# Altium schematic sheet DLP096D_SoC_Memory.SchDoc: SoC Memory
size 431 x 279 mm; Date: Not shown in title block; ApprovedBy: Not shown in title block; CheckedBy: Not shown in title block; Author: Not shown in title block; CompanyName: Not shown in title block; Engineer: Not shown in title block; Organization: Not shown in title block; Address1: Not shown in title block; Address2: Not shown in title block; Address3: Not shown in title block; Address4: Not shown in title block; DocumentNumber: 7; Revision: Use project parameter SCH_Rev; SheetNumber: 7; SheetTotal: 10; PageSetup: Record=PageOptions¦CenterHorizontal=True¦CenterVertical=True¦PrintScale=1.00¦XCorrection=1.00¦YCorrection=1.00¦PrintKind=0¦BorderSize=5000000¦LeftOffset=0¦BottomOffset=0¦Orientation=2¦PaperLength=1000¦PaperWidth=1000¦Scale=100¦PaperSource=15¦PrintQuality=600¦MediaType=1¦DitherType=10¦PaperKind=Letter¦PrintScaleMode=1
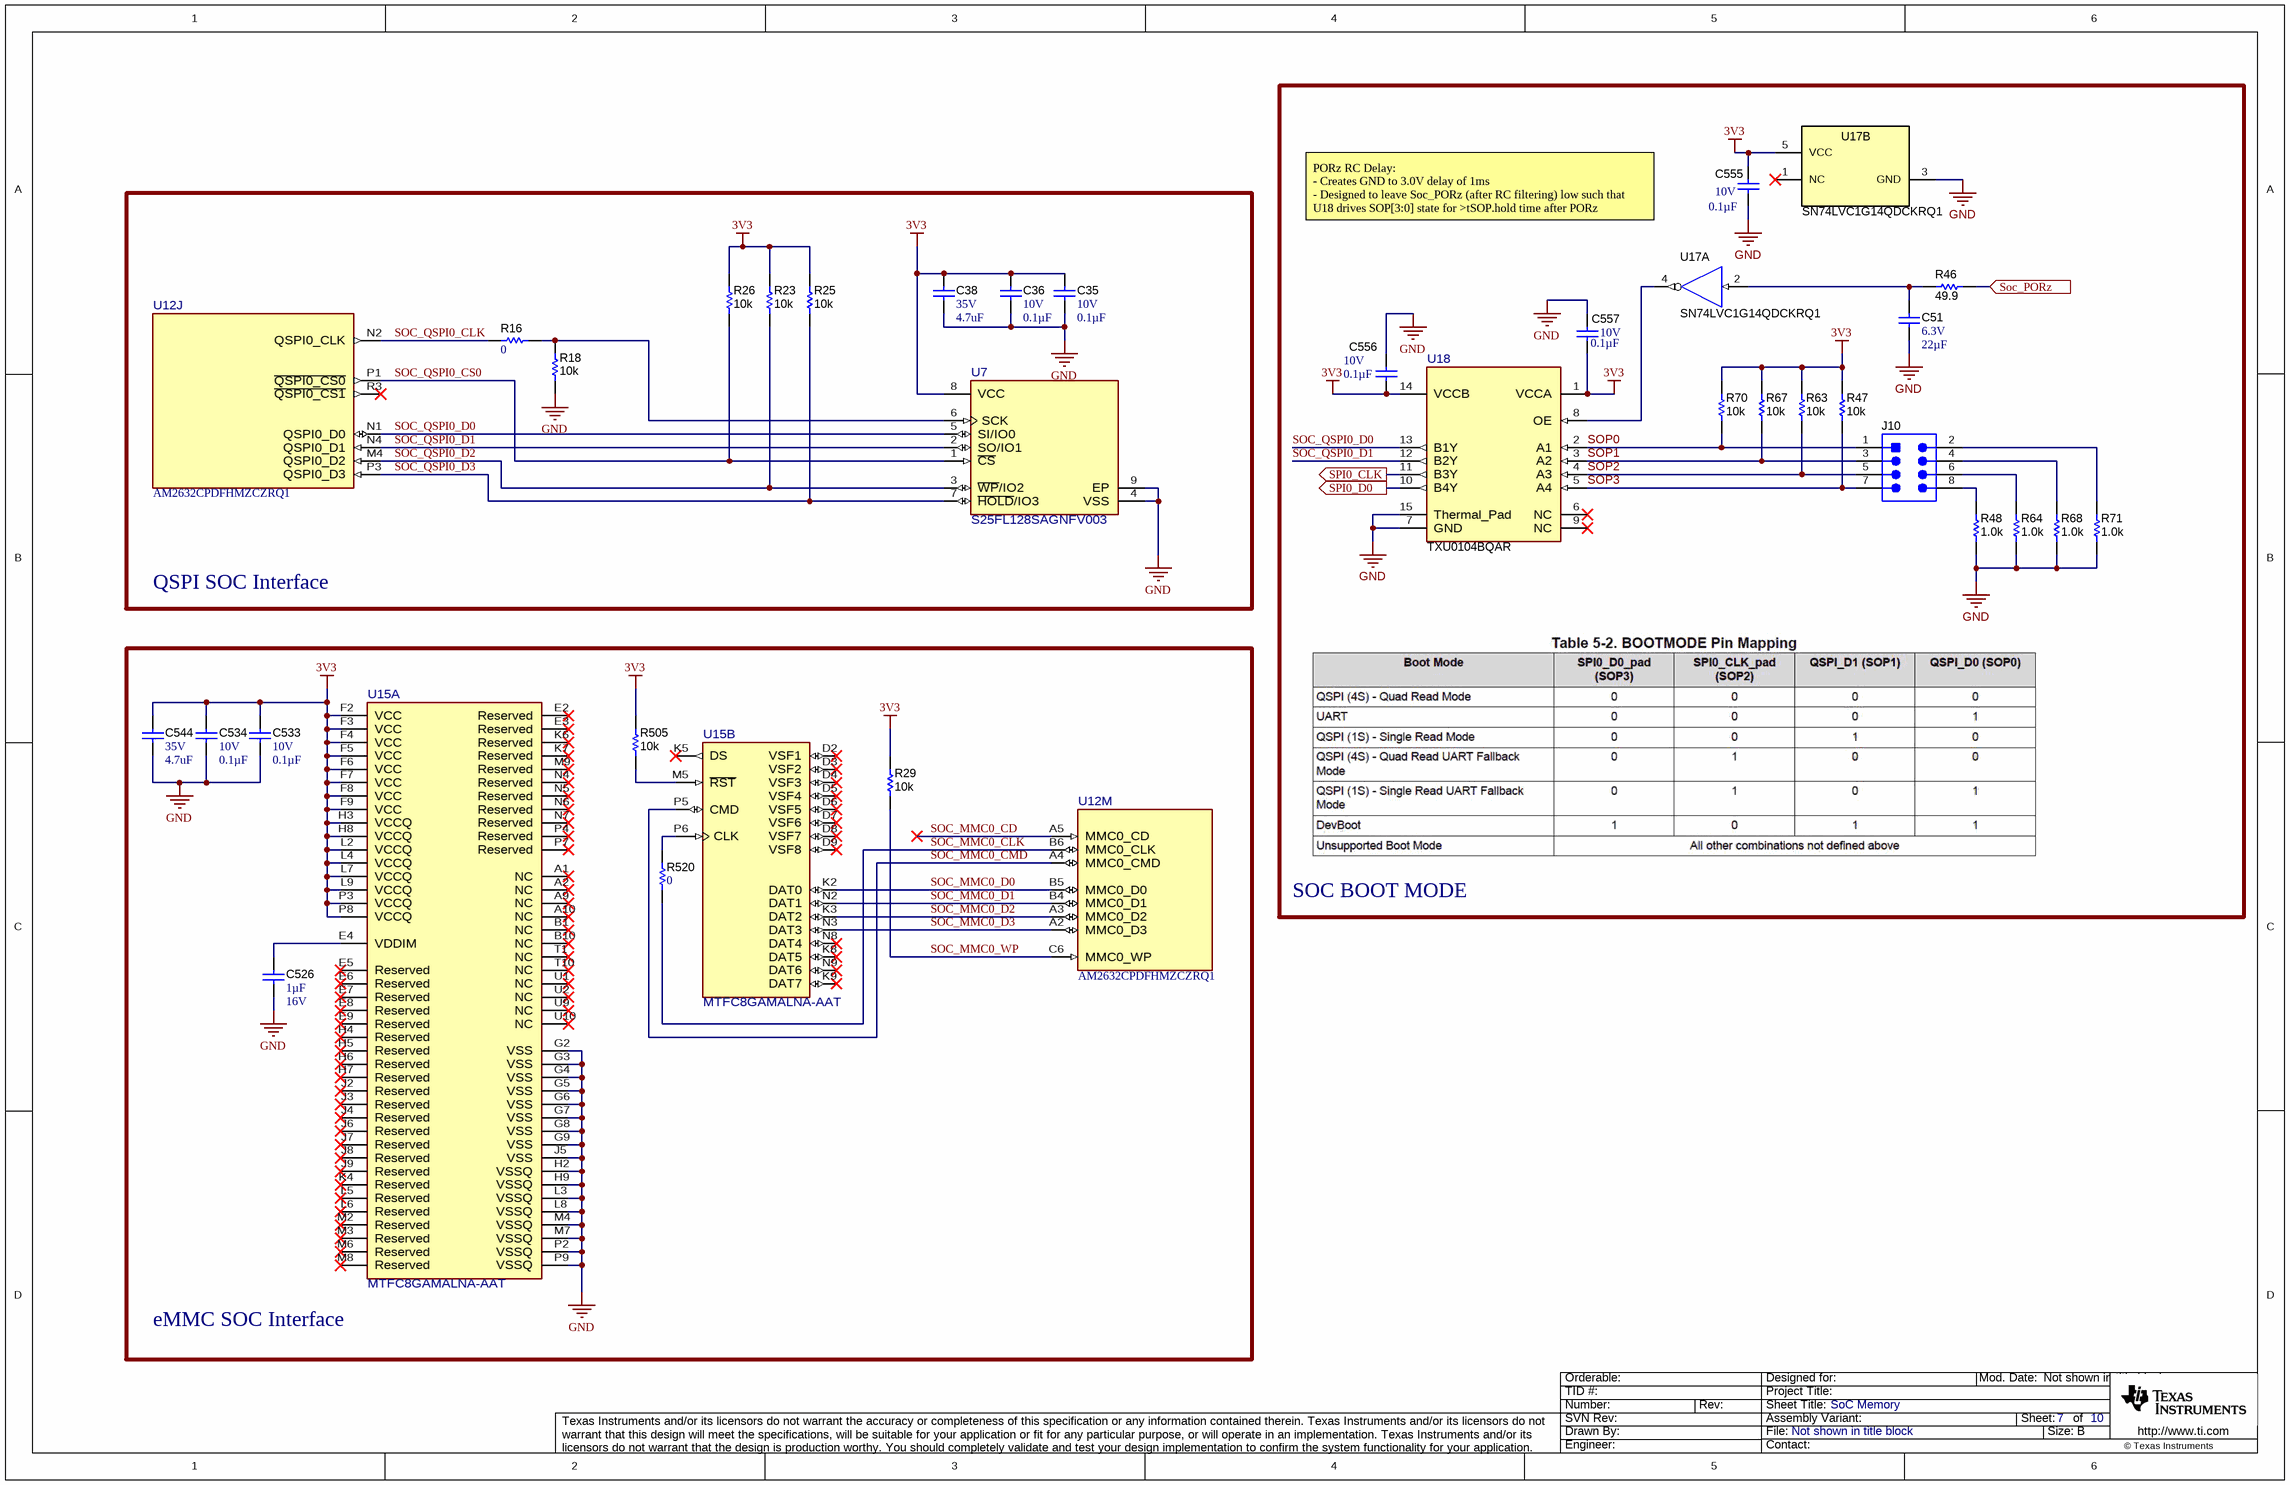
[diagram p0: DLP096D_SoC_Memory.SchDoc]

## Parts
C35  VDC_V: 10V  ValueDisplayed: 0.1µF  [0201_033]  (hidden comment: GRM033R61A104KE84D)
C36  VDC_V: 10V  ValueDisplayed: 0.1µF  [0201_033]  (hidden comment: GRM033R61A104KE84D)
C38  VDC_V: 35V  ValueDisplayed: 4.7uF  [0603]  (hidden comment: C1608X5R1V475K080AC)
C51  VDC_V: 6.3V  ValueDisplayed: 22µF  [0603]  (hidden comment: GRM186R60J226ME15D)
C526  Cap_F: 1µF  VDC_V: 16V  [0603]  (hidden comment: CGA3E1X7R1C105K080AC)
C533  VDC_V: 10V  ValueDisplayed: 0.1µF  [0201_033]  (hidden comment: GRM033R61A104KE84D)
C534  VDC_V: 10V  ValueDisplayed: 0.1µF  [0201_033]  (hidden comment: GRM033R61A104KE84D)
C544  VDC_V: 35V  ValueDisplayed: 4.7uF  [0603]  (hidden comment: C1608X5R1V475K080AC)
C555  VDC_V: 10V  ValueDisplayed: 0.1µF  [0402]  (hidden comment: C0402C104K8RACTU)
C556  VDC_V: 10V  ValueDisplayed: 0.1µF  [0402]  (hidden comment: C0402C104K8RACTU)
C557  VDC_V: 10V  ValueDisplayed: 0.1µF  [0402]  (hidden comment: C0402C104K8RACTU)
J10  TSM-104-01-L-DV  [Samtec_TSM-104-01-x-DV]  (value not drawn)
R16  ValueDisplayed: 0  [0402]  (hidden comment: MCR01MZPJ000)
R18  ValueDisplayed: 10k  [0201]  (hidden comment: RC0201JR-0710KL)
R23  ValueDisplayed: 10k  [0201]  (hidden comment: RC0201JR-0710KL)
R25  ValueDisplayed: 10k  [0201]  (hidden comment: RC0201JR-0710KL)
R26  ValueDisplayed: 10k  [0201]  (hidden comment: RC0201JR-0710KL)
R29  ValueDisplayed: 10k  [0201]  (hidden comment: RC0201JR-0710KL)
R46  ValueDisplayed: 49.9  [0603]  (hidden comment: ERJ-3EKF49R9V)
R47  ValueDisplayed: 10k  [0201]  (hidden comment: RC0201JR-0710KL)
R48  ValueDisplayed: 1.0k  [0402L]  (hidden comment: ERJ-2GEJ102X)
R63  ValueDisplayed: 10k  [0201]  (hidden comment: RC0201JR-0710KL)
R64  ValueDisplayed: 1.0k  [0402L]  (hidden comment: ERJ-2GEJ102X)
R67  ValueDisplayed: 10k  [0201]  (hidden comment: RC0201JR-0710KL)
R68  ValueDisplayed: 1.0k  [0402L]  (hidden comment: ERJ-2GEJ102X)
R70  ValueDisplayed: 10k  [0201]  (hidden comment: RC0201JR-0710KL)
R71  ValueDisplayed: 1.0k  [0402L]  (hidden comment: ERJ-2GEJ102X)
R505  ValueDisplayed: 10k  [0201]  (hidden comment: RC0201JR-0710KL)
R520  ValueDisplayed: 0  [0402]  (hidden comment: MCR01MZPJ000)
U7  S25FL128SAGNFV003  [FP-S25FL128SAGNFI000_WSON8-MFG]
U12  PartNumber: AM2632CPDFHMZCZRQ1  [ZCZ0324A-MFG]  (hidden comment: XAM2634AOLFGMZCZQ)  (parts J,M of 13)
U15  MTFC8GAMALNA-AAT  [FP-MTFC128GAPALNA-AAT_TBGA100-MFG]  (parts A,B of 2)
U17  SN74LVC1G14QDCKRQ1  [DCK0005A_N]  (parts A,B of 2)
U18  TXU0104BQAR  [BQA0014A-MFG]

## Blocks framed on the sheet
SOC BOOT MODE: C51 C555-C557 J10 R46-R48 R63 R64 R67 R68 R70 R71 U17 U18
QSPI SOC Interface: C35 C36 C38 R16 R18 R23 R25 R26 U7 U12
eMMC SOC Interface: C526 C533 C534 C544 R29 R505 R520 U12 U15

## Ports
Soc_PORz (in), SPI0_CLK (out), SPI0_D0 (out)

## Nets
3V3: C35.1 C36.1 C38.1 C533.1 C534.1 C544.1 C555.1 C556.1 C557.2 R23.2 R25.2 R26.2 R29.2 R47.2 R63.2 R67.2 R70.2 R505.2 U7.8(VCC) U15.F2(VCC) U15.F3(VCC) U15.F4(VCC) U15.F5(VCC) U15.F6(VCC) U15.F7(VCC) U15.F8(VCC) U15.F9(VCC) U15.H3(VCCQ) U15.H8(VCCQ) U15.L2(VCCQ) U15.L4(VCCQ) U15.L7(VCCQ) U15.L9(VCCQ) U15.P3(VCCQ) U15.P8(VCCQ) U17.5(VCC) U18.1(VCCA) U18.14(VCCB)
GND: C35.2 C36.2 C38.2 C51.2 C526.2 C533.2 C534.2 C544.2 C555.2 C556.2 C557.1 R18.1 R48.1 R64.1 R68.1 R71.1 U7.4(VSS) U7.9(EP) U15.G2(VSS) U15.G3(VSS) U15.G4(VSS) U15.G5(VSS) U15.G6(VSS) U15.G7(VSS) U15.G8(VSS) U15.G9(VSS) U15.H2(VSSQ) U15.H9(VSSQ) U15.J5(VSS) U15.L3(VSSQ) U15.L8(VSSQ) U15.M4(VSSQ) U15.M7(VSSQ) U15.P2(VSSQ) U15.P9(VSSQ) U17.3(GND) U18.7(GND) U18.15(Thermal_Pad)
SOC_MMC0_CD: U12.A5(MMC0_CD)
SOC_MMC0_CLK: R520.1 U12.B6(MMC0_CLK)
SOC_MMC0_CMD: U12.A4(MMC0_CMD) U15.P5(CMD)
SOC_MMC0_D0: U12.B5(MMC0_D0) U15.K2(DAT0)
SOC_MMC0_D1: U12.B4(MMC0_D1) U15.N2(DAT1)
SOC_MMC0_D2: U12.A3(MMC0_D2) U15.K3(DAT2)
SOC_MMC0_D3: U12.A2(MMC0_D3) U15.N3(DAT3)
SOC_MMC0_WP: R29.1 U12.C6(MMC0_WP)
Soc_PORz: R46.2 ; port Soc_PORz
SOC_QSPI0_CLK: R16.1 U12.N2(QSPI0_CLK)
SOC_QSPI0_CS0: R26.1 U7.1(~{CS}) U12.P1(~{QSPI0_CS0})
SOC_QSPI0_D0: U7.5(SI/IO0) U12.N1(QSPI0_D0) U18.13(B1Y)
SOC_QSPI0_D1: U7.2(SO/IO1) U12.N4(QSPI0_D1) U18.12(B2Y)
SOC_QSPI0_D2: R23.1 U7.3(~{WP}/IO2) U12.M4(QSPI0_D2)
SOC_QSPI0_D3: R25.1 U7.7(~{HOLD}/IO3) U12.P3(QSPI0_D3)
SOP0: J10.1 R70.1 U18.2(A1)
SOP1: J10.3 R67.1 U18.3(A2)
SOP2: J10.5 R63.1 U18.4(A3)
SOP3: J10.7 R47.1 U18.5(A4)
SPI0_CLK: U18.11(B3Y) ; port SPI0_CLK
SPI0_D0: U18.10(B4Y) ; port SPI0_D0
NetC51_1: C51.1 R46.1 U17.2(A)
NetC526_1: C526.1 U15.E4(VDDIM)
NetJ10_2: J10.2 R71.2
NetJ10_4: J10.4 R68.2
NetJ10_6: J10.6 R64.2
NetJ10_8: J10.8 R48.2
NetR16_2: R16.2 R18.2 U7.6(SCK)
NetR505_1: R505.1 U15.M5(~{RST})
NetR520_2: R520.2 U15.P6(CLK)
NetU17_4: U17.4(Y) U18.8(OE)

Not connected (* = marked no-connect by the designer): U12 R3(~{QSPI0_CS1})*; U15 A1(NC)* A2(NC)* A9(NC)* A10(NC)* B1(NC)* B10(NC)* D2(VSF1)* D3(VSF2)* D4(VSF3)* D5(VSF4)* D6(VSF5)* D7(VSF6)* D8(VSF7)* D9(VSF8)* E2(Reserved)* E3(Reserved)* E5(Reserved)* E6(Reserved)* E7(Reserved)* E8(Reserved)* E9(Reserved)* H4(Reserved)* H5(Reserved)* H6(Reserved)* H7(Reserved)* J2(Reserved)* J3(Reserved)* J4(Reserved)* J6(Reserved)* J7(Reserved)* J8(Reserved)* J9(Reserved)* K4(Reserved)* K5(DS)* K6(Reserved)* K7(Reserved)* K8(DAT5)* K9(DAT7)* L5(Reserved)* L6(Reserved)* M2(Reserved)* M3(Reserved)* M6(Reserved)* M8(Reserved)* M9(Reserved)* N4(Reserved)* N5(Reserved)* N6(Reserved)* N7(Reserved)* N8(DAT4)* N9(DAT6)* P4(Reserved)* P7(Reserved)* T1(NC)* T10(NC)* U1(NC)* U2(NC)* U9(NC)* U10(NC)*; U17 1(NC)*; U18 6(NC)* 9(NC)*

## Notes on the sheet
- PORz RC Delay:
  - Creates GND to 3.0V delay of 1ms
  - Designed to leave Soc_PORz (after RC filtering) low such that U18 drives SOP[3:0] state for >tSOP.hold time after PORz de-assertion

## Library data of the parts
C35 C36 C533 C534 = CMP-0086059-1: CAP, CERM, 0.1 µF, 10 V,+/- 10%, X5R, 0201; Manufacturer: MuRata; AEC Category: Q200; Cap_F: 100nF; Value: 0.1uF; SizeY_mm: 0.3; AEC Qualified: N; SizeAreaWB_mm2: 2.08; Cap_Case: 0201; SizeArea_mm2: 0.18; SizeZ_mm: 0.33; SizeX_mm: 0.6; TaMax_C: 85°C; TaMin_C: -55°C; U/M: EA
C38 C544 = CMP-0007022-5: CAP, CERM, 4.7 uF, 35 V, +/- 10%, X5R, 0603; Manufacturer: TDK; TaMin_C: -55°C; ESR_ohm: 3.728m; Polarized: N; SizeAreaWB_mm2: 4.68; Value1: 0.003728 ohm; U/M: EA; Value: 4.7uF; TaMax_C: 85°C; SizeZ_mm: 1; SizeX_mm: 1.6; SizeY_mm: 0.8; SizeArea_mm2: 1.28; Cap_F: 4.7µF; IRMS_A: 2.6936A; AEC Category: Q200
C51 = CMP-0078295-1: CAP, CERM, 22 µF, 6.3 V,+/- 20%, X5R, 0603; Manufacturer: MuRata; TaMin_C: -55°C; Polarized: N; SizeAreaWB_mm2: 4.68; U/M: EA; Value: 22uF; TaMax_C: 85°C; SizeZ_mm: 1; SizeX_mm: 1.6; SizeY_mm: 0.8; SizeArea_mm2: 1.28; AEC Category: Q200
C526 = CMP-0079607-1: CAP, CERM, 1 µF, 16 V,+/- 10%, X7R, AEC-Q200 Grade 1, 0603; Manufacturer: TDK; TaMin_C: -55°C; Polarized: N; SizeAreaWB_mm2: 4.68; U/M: EA; Value: 1uF; TaMax_C: 125°C; SizeZ_mm: 1; SizeX_mm: 1.6; SizeY_mm: 0.8; SizeArea_mm2: 1.28; AEC Qualified: Y; AEC Category: Q200
C555-C557 = CMP-0078241-1: CAP, CERM, 0.1 µF, 10 V,+/- 10%, X7R, 0402; Manufacturer: Kemet; TaMin_C: -55°C; Polarized: N; SizeAreaWB_mm2: 3; U/M: EA; Value: 0.1uF; TaMax_C: 125°C; SizeZ_mm: 0.6; SizeX_mm: 1; SizeY_mm: 0.5; Cap_F: 100nF; AEC Category: Q200
J10 = CMP-0075593-2: Header, 2.54mm, 4x2, Gold, SMT; Manufacturer: Samtec; Pitch_mm: 2.54; Gender: Male; Cert_CSA: Y; Green_REACh: Passed; Current_A: 4.9A; Voltage_V: 475V; Shrouded: N; Green_Lifecycle: Active; Row_Count: 2
R16 R520 = CMP-0027002-2: RES, 0, 5%, 0.063 W, 0402; Manufacturer: Rohm; Power_W: 63mW; TempCo: 500 ppm/C; Value_Code: 0000; U/M: EA; Value: 0; EIA_Code: E24; SizeX_mm: 1; SizeY_mm: 0.5; SizeZ_mm: 0.6; Value2: 0.063W; VDC_V: 50V; AEC Category: Q200
R18 R23 R25 R26 R29 R47 R63 R67 R70 R505 = CMP-0027019-1: RES, 10 k, 5%, 0.05 W, 0201; Manufacturer: Yageo America; Power_W: 50mW; TempCo: 200 ppm/C; Value_Code: 10k0; U/M: EA; Value: 10k; EIA_Code: E24; SizeX_mm: 0.6; SizeY_mm: 0.3; SizeZ_mm: 0.26; Value2: 0.05W; SizeArea_mm2: 0.18; AEC Qualified: N; VDC_V: 25V; AEC Category: Q200
R46 = CMP-0022707-2: RES, 49.9, 1%, 0.1 W, AEC-Q200 Grade 0, 0603; Manufacturer: Panasonic; Power_W: 100mW; Value_Code: 49R9; U/M: EA; Value: 49.9; EIA_Code: E96; TempCo: 100 ppm/C; SizeX_mm: 1.6; SizeY_mm: 0.8; SizeZ_mm: 1; Value2: 0.1W; SizeArea_mm2: 1.28; AEC Qualified: Y; AEC Grade: 0; AEC Category: Q200
R48 R64 R68 R71 = CMP-0078193-1: RES, 1.0 k, 5%, 0.1 W, AEC-Q200 Grade 0, 0402; Manufacturer: Panasonic; Value_Code: 1k00; SizeArea_mm2: 0.5; AEC Qualified: Y; AEC Category: Q200; Res_ohm: 1k; Value: 1.0k; SizeZ_mm: 0.6; Green_REACh: Passed; EIA_Code: E24; TempCo: 200 ppm/C; AEC Grade: 0; Power_W: 100mW; VDC_V: 50V; Value2: 0.1W; Green_Lifecycle: Active; U/M: EA; SizeX_mm: 1
U7 = CMP-0093537-1: FLASH - NOR Memory IC 128Mb (16M x 8) SPI - Quad I/O 133 MHz 8-WSON (6x8); Manufacturer: Cypress Semiconductor; Nominal Supply Current: 16-100mA; AEC Qualified: Yes; Max Supply Voltage: 3.6V; Access Time: 8ns; TaMin_C: -40°C; SizeZ_mm: 0.8mm; TaMax_C: +105°C; Standoff Height: 0mm; Memory Size: 128Mbits; Min Supply Voltage: 1.65V; Frequency_Fixed: 133MHz
U12 = CMP-0093674-1: Sitara™ Microcontrollers; Manufacturer: Texas Instruments; Min Supply Voltage: 1.14V; Number Of Adc Channels: 30; AEC Qualified: No; TJmax_C: +105°C; Memory Type: SRAM; Standoff Height: 0.35mm; Core Architecture: ARM Cortex-R5F; Number Of I2C Channels: 4; Number Of Pwm Channels: 24; Number Of Spi Channels: 5; Number Of Cores: 2; Frequency_Fixed: 400MHz; Nominal Supply Current: 200-2500mA; Ram Size: 2MBytes; Number Of Ethernet Channels: 1; Interface: I2C,SPI,UART,CAN,LIN,Ethernet,Other; Data Bus Width: 64bits; SizeZ_mm: 1.4mm; Number Of Uart Channels: 6; Number Of I/Os: 140; Max Supply Voltage: 3.465V
U15 = CMP-0088841-1: e.MMC Memory, 8GB NOR FLASH memory; Manufacturer: Micron; Frequency_Fixed: 200MHz; TaMax_C: +105°C; Standoff Height: 0.316mm; AEC Grade: Grade 2; TaMin_C: -40°C; AEC Qualified: Yes; Nominal Supply Current: 90-150mA; Interface: Other; Memory Size: 8GBytes; SizeZ_mm: 1.2mm; Max Supply Voltage: 3.6V; Min Supply Voltage: 1.7V; Memory Type: FLASH,NAND
U17 = CMP-0082079-1: Automotive Single Schmitt-Trigger Inverter, DCK0005A (SOT-SC70-5); Alternate Manufacturer: Texas Instruments; SizeAreaWB_mm2: 9.3; SizeZ_mm: 1.1; SizeX_mm: 2.1; SizeY_mm: 2; SizeArea_mm2: 4.2; CompType: IC; AEC Qualified: Y; AEC Category: Q200
U18 = CMP-0095233-1: Four channel unidirectional level shifter 14-WQFN -40 to 125; Manufacturer: Texas Instruments; V B Min: 1.08V; TaMin_C: -40°C; AEC Qualified: No; TaMax_C: +125°C; Propagation Delay: 8ns; Data Rate: 200Mbits/s; Standoff Height: 0mm; TJmax_C: +150°C; SizeZ_mm: 0.8mm; PositionCount: 1; V A Max: 5.5V; Number Of Inputs: 4; Nominal Supply Current: 2.5uA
